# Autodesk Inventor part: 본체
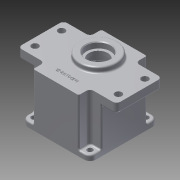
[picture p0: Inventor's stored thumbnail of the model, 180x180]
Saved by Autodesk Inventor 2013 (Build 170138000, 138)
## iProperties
Created: 2015-07
Part Number: 본체
Material: 알루미늄 6061
Document SubType Name: Modeling
Designer: user
Density: 2.71 g/cm^3
Mass: 704.918 g
Surface Area: 674.48 cm^2
Volume: 260.117 cm^3
Author: user
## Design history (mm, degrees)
sketch "스케치1"
  geometry: L1 (-45, 45)-(45, 45); L2 (45, 45)-(45, -45); L3 (45, -45)-(-45, -45); L4 (-45, -45)-(-45, 45); 3 further points
  constraints: 8 end point, 2 midpoint, 2 parallel, 1 horizontal, 1 horizontal alignment, 1 perpendicular, 1 vertical alignment
  dimensions: "d0" = 90 distance of L1.start L1.end; "d2" = 90 distance of L1.end L2.end
extrude "돌출1" new body sketch "스케치1" distance "d3" = 7; taper "d4" = 0 deg
sketch "스케치2"
  geometry: L1 (45, 45)-(-45, 45) reference; L2 (-45, 45)-(-45, -45) reference; L3 (-45, -45)-(45, -45) reference; L4 (45, -45)-(45, 45) reference; L5 (-30, 45)-(30, 45); L6 (30, 45)-(30, -45); L7 (30, -45)-(-30, -45); L8 (-30, -45)-(-30, 45); L9 (-45, 30)-(45, 30); L10 (45, 30)-(45, -30); L11 (45, -30)-(-45, -30); L12 (-45, -30)-(-45, 30); 4 further points
  constraints: 16 end point, 4 parallel, 4 point on line, 3 midpoint, 2 horizontal, 2 perpendicular, 2 vertical alignment, 1 horizontal alignment
  dimensions: "d5" = 60 distance of L5.start L5.end; "d7" = 60 distance of L11.end L9.start
extrude "돌출2" join sketch "스케치2" distance "d8" = 63; taper "d9" = 0 deg
sketch "스케치3"
  geometry: L1 (-65, 30)-(65, 30); L2 (65, 30)-(65, -30); L3 (65, -30)-(-65, -30); L4 (-65, -30)-(-65, 30); 3 further points
  constraints: 8 end point, 2 midpoint, 2 parallel, 1 horizontal, 1 horizontal alignment, 1 perpendicular, 1 vertical alignment
  dimensions: "d10" = 60 distance of L3.end L1.start; "d12" = 130 distance of L1.start L1.end
extrude "돌출3" join sketch "스케치3" distance "d13" = 12; taper "d14" = 0 deg
fillet "모깎기1" dims "d15" = 5
sketch "스케치4"
  geometry: L1 (-35, -30)-(-65, -30) reference; L2 (0, 0)-(0, 9.418); L3 (0, 0)-(20.166, 0); C1 r 4.5 at (55, 17.5); C2 r 4.5 at (-55, 17.5); C3 r 4.5 at (-55, -17.5); C4 r 4.5 at (55, -17.5)
  constraints: 4 centre point, 4 end point, 3 symmetric about line, 2 perpendicular, 3 other
  dimensions: "d16" = 9 diameter of C1; "d17" = 110 diameter of C1.centre L2; "d18" = 35 diameter of C1.centre L3
extrude "돌출4" cut sketch "스케치4" distance "d19" = 12; taper "d20" = 0 deg
sketch "스케치5"
  geometry: L1 (45, -45)-(45, 45) reference; L2 (0, 0)-(0, 11.26); L3 (0, 0)-(11.158, 0); C1 r 3.5 at (37, 37); C2 r 3.5 at (-37, 37); C3 r 3.5 at (-37, -37); C4 r 3.5 at (37, -37)
  constraints: 4 centre point, 4 end point, 3 symmetric about line, 1 parallel, 1 perpendicular, 3 other
  dimensions: "d21" = 7 diameter of C1; "d22" = 74 diameter of C1.centre L2; "d23" = 74 diameter of C1.centre L3
extrude "돌출5" cut sketch "스케치5" distance "d24" = 12; taper "d25" = 0 deg
sketch "스케치6"
  geometry: C1 r 40 at (0, 0); 1 further point
  constraints: 1 centre point, 1 coincident
  dimensions: "d26" = 80 diameter of C1
extrude "돌출6" cut sketch "스케치6" distance "d27" = 9; taper "d28" = 0 deg
sketch "스케치7"
  geometry: C1 r 40 at (0, 0) reference; C2 r 39 at (0, 0)
  constraints: 1 centre point, 1 coincident
  dimensions: "d29" = 78 diameter of C2
extrude "돌출7" cut sketch "스케치7" distance "d30" = 52; taper "d31" = 0 deg
sketch "스케치8"
  geometry: L1 (0, 0)-(13.503, 0); L2 (0, 0)-(0, 6.492); L3 (24.749, 24.749)-(-24.749, -24.749); L4 (-24.749, 24.749)-(24.749, -24.749); C1 r 40 at (0, 0) reference; A1 r 39 centre (0, 0) between (21.134, 32.777) and (32.777, 21.134) reference; A2 r 4 centre (24.749, 24.749) between (21.809, 27.462) and (27.462, 21.809); A3 r 3.5 centre (29.836, 19.238) between (32.777, 21.134) and (27.412, 21.762); A4 r 3.5 centre (19.238, 29.836) between (21.762, 27.412) and (21.134, 32.777); 1 further point
  constraints: 10 point on circle, 8 end point, 3 centre point, 3 coincident, 2 midpoint, 2 tangent, 1 horizontal, 1 perpendicular, 1 symmetric about line, 1 other
  dimensions: "d33" = 45 deg angle of L3 L2; "d35" = 45 deg angle of L4 L2; "d37" = 8 diameter of A2; "d38" = 7 diameter of A3
extrude "돌출8" join sketch "스케치8" distance "d39" = 52; taper "d40" = 0 deg
sketch "스케치9"
  geometry: A1 r 39 centre (0, 0) between (-32.777, 21.134) and (-32.777, -21.134) reference; A2 r 39 centre (0, 0) between (-21.134, -32.777) and (21.134, -32.777) reference; A3 r 39 centre (0, 0) between (32.777, -21.134) and (32.777, 21.134) reference; A4 r 20.5 centre (0, 11) between (11.115, -6.225) and (-11.115, -6.225); A5 r 14 centre (0, -20) between (-10.493, -10.732) and (10.493, -10.732); A6 r 3 centre (-12.742, -8.746) between (-10.493, -10.732) and (-11.115, -6.225); A7 r 3 centre (12.742, -8.746) between (11.115, -6.225) and (10.493, -10.732)
  constraints: 8 point on circle, 4 centre point, 4 tangent, 2 vertical alignment
  dimensions: "d44" = 41 diameter of A4; "d45" = 11 distance of A3.centre A4.centre; "d46" = 28 diameter of A5; "d47" = 20 distance of A5.centre A1.centre; "d48" = 6 diameter of A6; "d49" = 6 diameter of A7
extrude "돌출9" join sketch "스케치9" distance "d50" = 7; taper "d51" = 0 deg
sketch "스케치10"
  geometry: C1 r 17.5 at (0, 11); A1 r 20.5 centre (0, 11) between (11.115, -6.225) and (-11.115, -6.225) reference; 1 further point
  constraints: 1 centre point, 1 coincident
  dimensions: "d52" = 35 diameter of C1
extrude "돌출10" cut sketch "스케치10" distance "d53" = 10; taper "d54" = 0 deg
sketch "스케치11"
  geometry: C1 r 17.5 at (0, 0) reference; C2 r 12.5 at (0, 0); 1 further point
  constraints: 1 centre point, 1 coincident
  dimensions: "d55" = 25 diameter of C2
extrude "돌출11" cut sketch "스케치11" distance "d56" = 5; taper "d57" = 0 deg
sketch "스케치12"
  geometry: C1 r 12.5 at (0, 0) reference; C2 r 16 at (0, 0); 1 further point
  constraints: 1 centre point, 1 coincident
  dimensions: "d58" = 32 diameter of C2
extrude "돌출12" cut sketch "스케치12" distance "d59" = 8; taper "d60" = 0 deg
sketch "스케치13"
  geometry: C1 r 11 at (0, -20); A1 r 14 centre (0, -20) between (-10.493, -10.732) and (10.493, -10.732) reference; 1 further point
  constraints: 1 centre point, 1 coincident
  dimensions: "d61" = 22 diameter of C1
extrude "돌출13" cut sketch "스케치13" distance "d62" = 7; taper "d63" = 0 deg
sketch "스케치14"
  geometry: C1 r 11 at (0, 0) reference; C2 r 9.5 at (0, 0); 1 further point
  constraints: 1 centre point, 1 coincident
  dimensions: "d64" = 19 diameter of C2
extrude "돌출14" cut sketch "스케치14" distance "d65" = 1; taper "d66" = 0 deg
sketch "스케치15"
  geometry: C1 r 16 at (0, 11) reference; C2 r 25 at (0, 11); 1 further point
  constraints: 1 centre point, 1 coincident
  dimensions: "d67" = 50 diameter of C2
extrude "돌출15" join sketch "스케치15" distance "d68" = 7; taper "d69" = 0 deg
sketch "스케치16"
  geometry: A1 r 4 centre (24.749, -24.749) between (27.462, -21.809) and (21.809, -27.462) reference; A2 r 4 centre (-24.749, -24.749) between (-21.809, -27.462) and (-27.462, -21.809) reference; A3 r 4 centre (-24.749, 24.749) between (-27.462, 21.809) and (-21.809, 27.462) reference; A4 r 4 centre (24.749, 24.749) between (21.809, 27.462) and (27.462, 21.809) reference; 4 further points
  constraints: 4 coincident
hole "구멍1" sketch "스케치16" at (24.749, 24.749), (24.749, -24.749), (-24.749, -24.749), (-24.749, 24.749) diameter "d70" = 3.459; stored, may be unused: countersink angle "d74" = 90 deg, drill point angle "d76" = 118 deg; dims "d71" = 12, "d72" = 4, "d73" = 2, "d75" = 15
sketch "스케치17"
  geometry: L1 (-30, -45)-(30, -45) reference; 2 further points
  constraints: 1 vertical alignment, 1 other
  dimensions: "d77" = 15 distance from line of L1 point (0, -30)
feature "엠보싱1" sketch "스케치17" dims "d0" = 90, "d2" = 90, "d7" = 60, "d78" = 0.5, "d79" = 0
fillet "모깎기2" dims "d80" = 5
fillet "모깎기3" dims "d81" = 8
fillet "모깎기4" dims "d82" = 0.3
fillet "모깎기5" dims "d83" = 2
chamfer "모따기1" distance "d84" = 1; stored, may be unused: second distance "d85" = 2, angle "d86" = 45 deg
fillet "모깎기6" dims "d87" = 2
fillet "모깎기7" dims "d88" = 2
fillet "모깎기8" dims "d89" = 2
fillet "모깎기9" dims "d90" = 2
fillet "모깎기10" dims "d91" = 2
node "솔리드1"
pattern_circular "원형 패턴1" dims angle "d42" = 360 deg
